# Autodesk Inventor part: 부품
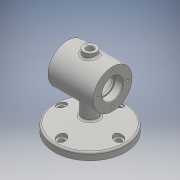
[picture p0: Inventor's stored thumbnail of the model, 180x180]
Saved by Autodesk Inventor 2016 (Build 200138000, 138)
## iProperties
Created: 2018-12
Part Number: 부품
Material: 일반
Document SubType Name: Modeling
Designer: USER
Density: 1 g/cm^3
Appearance: 기본값
Author: USER
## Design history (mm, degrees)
sketch "스케치1"
  geometry: C1 r 55 at (0, 0); 1 further point
  constraints: 1 centre point, 1 coincident
  dimensions: "d0" = 110 diameter of C1
extrude "돌출1" new body sketch "스케치1" distance "d1" = 11; taper "d2" = 0 deg
sketch "스케치2"
  geometry: L1 (35, 75)-(-35, 75); L2 (35, 75)-(35, 105); L3 (35, 105)-(-35, 105); L4 (-35, 105)-(-35, 75); L5 (-55, 0)-(55, 0) reference; L6 (55, 11)-(-55, 11) reference; 2 further points
  constraints: 8 end point, 1 horizontal, 1 midpoint, 1 perpendicular, 1 vertical, 1 vertical alignment
  dimensions: "d3" = 70 distance of L1.start L1.end; "d4" = 30 distance of L1.start L2.end; "d5" = 70 distance of L2.end L3.end; "d6" = 75 distance from line of point (0, 0) L1; "d77" = 11 distance between parallel lines of L5 L6 (derived)
revolve "회전1" sketch "스케치2" stored, may be unused: angle "d7" = 90 deg
node "작업 평면1"
sketch "스케치3"
  geometry: C1 r 10 at (0, 0); 1 further point
  constraints: 1 centre point, 1 coincident
  dimensions: "d9" = 20 diameter of C1
extrude "돌출2" join sketch "스케치3" distance "d10" = 37; taper "d11" = 0 deg
sketch "스케치4"
  geometry: L1 (64, 55)-(64, -55) reference; L2 (75, -55)-(75, 55) reference; C1 r 30 at (0, 0) reference; C2 r 16 at (0, 0); 1 further point
  constraints: 1 centre point, 1 coincident
  dimensions: "d12" = 32 diameter of C2; "d78" = 11 distance between parallel lines of L1 L2 (derived)
extrude "돌출3" cut sketch "스케치4" distance "d13" = 12; taper "d14" = 0 deg
sketch "스케치5"
  geometry: C1 r 16 at (0, 0) reference; C2 r 14 at (0, 0); 1 further point
  constraints: 1 centre point, 1 coincident
  dimensions: "d15" = 28 diameter of C2
extrude "돌출4" cut sketch "스케치5" distance "d16" = 3; taper "d17" = 0 deg
sketch "스케치6"
  geometry: C1 r 14 at (0, 0) reference; C2 r 25 at (0, 0); 1 further point
  constraints: 1 centre point, 1 coincident
  dimensions: "d18" = 50 diameter of C2
extrude "돌출5" cut sketch "스케치6" distance "d19" = 40; taper "d20" = 0 deg
sketch "스케치7"
  geometry: C1 r 30 at (0, 0) reference; C2 r 16 at (0, 0); 1 further point
  constraints: 1 centre point, 1 coincident
  dimensions: "d21" = 32 diameter of C2
extrude "돌출6" cut sketch "스케치7" distance "d22" = 12; taper "d23" = 0 deg
sketch "스케치8"
  geometry: C1 r 16 at (0, 0) reference; C2 r 14 at (0, 0); 1 further point
  constraints: 1 centre point, 1 coincident
  dimensions: "d24" = 28 diameter of C2
extrude "돌출7" cut sketch "스케치8" distance "d25" = 3; taper "d26" = 0 deg
sketch "스케치9"
  geometry: C1 r 5 at (0, 0); 1 further point
  constraints: 1 centre point, 1 coincident
  dimensions: "d27" = 10 diameter of C1
extrude "돌출8" cut sketch "스케치9" stored distance "d28" = 3; taper "d29" = 0 deg
sketch "스케치10"
  geometry: C1 r 12 at (0, 0); 1 further point
  constraints: 1 centre point, 1 coincident
  dimensions: "d30" = 24 diameter of C1
extrude "돌출9" join sketch "스케치10" stored distance "d31" = 3; taper "d32" = 0 deg
sketch "스케치11"
  geometry: L1 (55, 11)-(-55, 11) reference; L2 (-55, 0)-(55, 0) reference; L3 (55, 11)-(-55, 11) reference; L4 (-55, 11)-(0, 25.737); L5 (-55, 11)-(1.94, 11); L6 (0, 25.737)-(0, 0); L7 (-55, 0)-(55, 0) reference; L8 (-55, 0)-(-55, 11); L9 (-55, 0)-(-55, 11) reference; L10 (-55, 0)-(0, 0); 1 further point
  constraints: 10 end point, 2 collinear, 2 midpoint, 1 equal length, 1 horizontal, 1 vertical alignment
  dimensions: "d34" = 15 deg angle of L5 L4
revolve "회전2" sketch "스케치11" stored, may be unused: angle "d35" = 90 deg
sketch "스케치12"
  geometry: C1 r 16 at (0, 0) reference; C2 r 30 at (0, 0) reference; 2 further points
  constraints: 1 horizontal alignment
  dimensions: "d36" = 23 distance of C1.centre point (23, 0)
hole "구멍1" sketch "스케치12" at (23, 0) diameter "d37" = 3.242; stored, may be unused: countersink angle "d41" = 90 deg, drill point angle "d43" = 118 deg; dims "d38" = 8, "d39" = 4, "d40" = 2, "d42" = 10
sketch "스케치13"
  geometry: C1 r 16 at (0, 0) reference; C2 r 30 at (0, 0) reference; 2 further points
  constraints: 1 horizontal alignment
  dimensions: "d47" = 23 distance of C1.centre point (-23, 0)
hole "구멍2" sketch "스케치13" at (-23, 0) diameter "d48" = 3.242; stored, may be unused: countersink angle "d52" = 90 deg, drill point angle "d54" = 118 deg; dims "d49" = 8, "d50" = 4, "d51" = 2, "d53" = 10
sketch "스케치14"
  geometry: C1 r 4.5 at (-44, 0); 1 further point
  constraints: 1 centre point, 1 horizontal alignment
  dimensions: "d58" = 9 diameter of C1; "d59" = 44 distance of point (0, 0) C1.centre
extrude "돌출10" cut sketch "스케치14" distance "d60" = 10; taper "d61" = 0 deg
sketch "스케치15"
  geometry: C1 r 4.5 at (0, 0) reference; C2 r 7 at (0, 0); 1 further point
  constraints: 1 centre point, 1 coincident
  dimensions: "d62" = 14 diameter of C2
extrude "돌출11" cut sketch "스케치15" distance "d63" = 10; taper "d64" = 0 deg
node "작업 평면2"
sketch "스케치16"
  geometry: L1 (-35, -30)-(-35, 30) reference; L2 (-35, 30)-(35, 30) reference; 2 further points
  constraints: 1 other
  dimensions: "d68" = 35 distance from line of point (0, 0) L1; "d69" = 30 distance from line of point (0, 0) L2
feature "엠보싱1" sketch "스케치16" dims "d70" = 0.5, "d71" = 0
chamfer "모따기1" distance "d72" = 1; stored, may be unused: second distance "d73" = 2, angle "d74" = 45 deg
fillet "모깎기1" dims "d75" = 3
fillet "모깎기2" dims "d76" = 0.3
node "솔리드1"
pattern_circular "원형 패턴1" dims angle "d45" = 360 deg
pattern_circular "원형 패턴2" dims angle "d56" = 360 deg
pattern_circular "원형 패턴3" dims angle "d66" = 360 deg
node "투영된 루프1"
node "투영된 루프2"
node "투영된 루프3"
node "투영된 루프4"
node "투영된 루프5"
node "투영된 루프6"
node "투영된 루프7"
node "투영된 루프8"
node "투영된 루프9"
other parameters: "d8" = 75
